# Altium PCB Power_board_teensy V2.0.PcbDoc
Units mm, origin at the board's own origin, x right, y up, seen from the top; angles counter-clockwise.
Board outline 76.2 x 50.8 mm, 2 copper layers (Top, Bottom), stack 1.572 mm thick; 21 components, 7 nets, 53 pads, 0 vias.
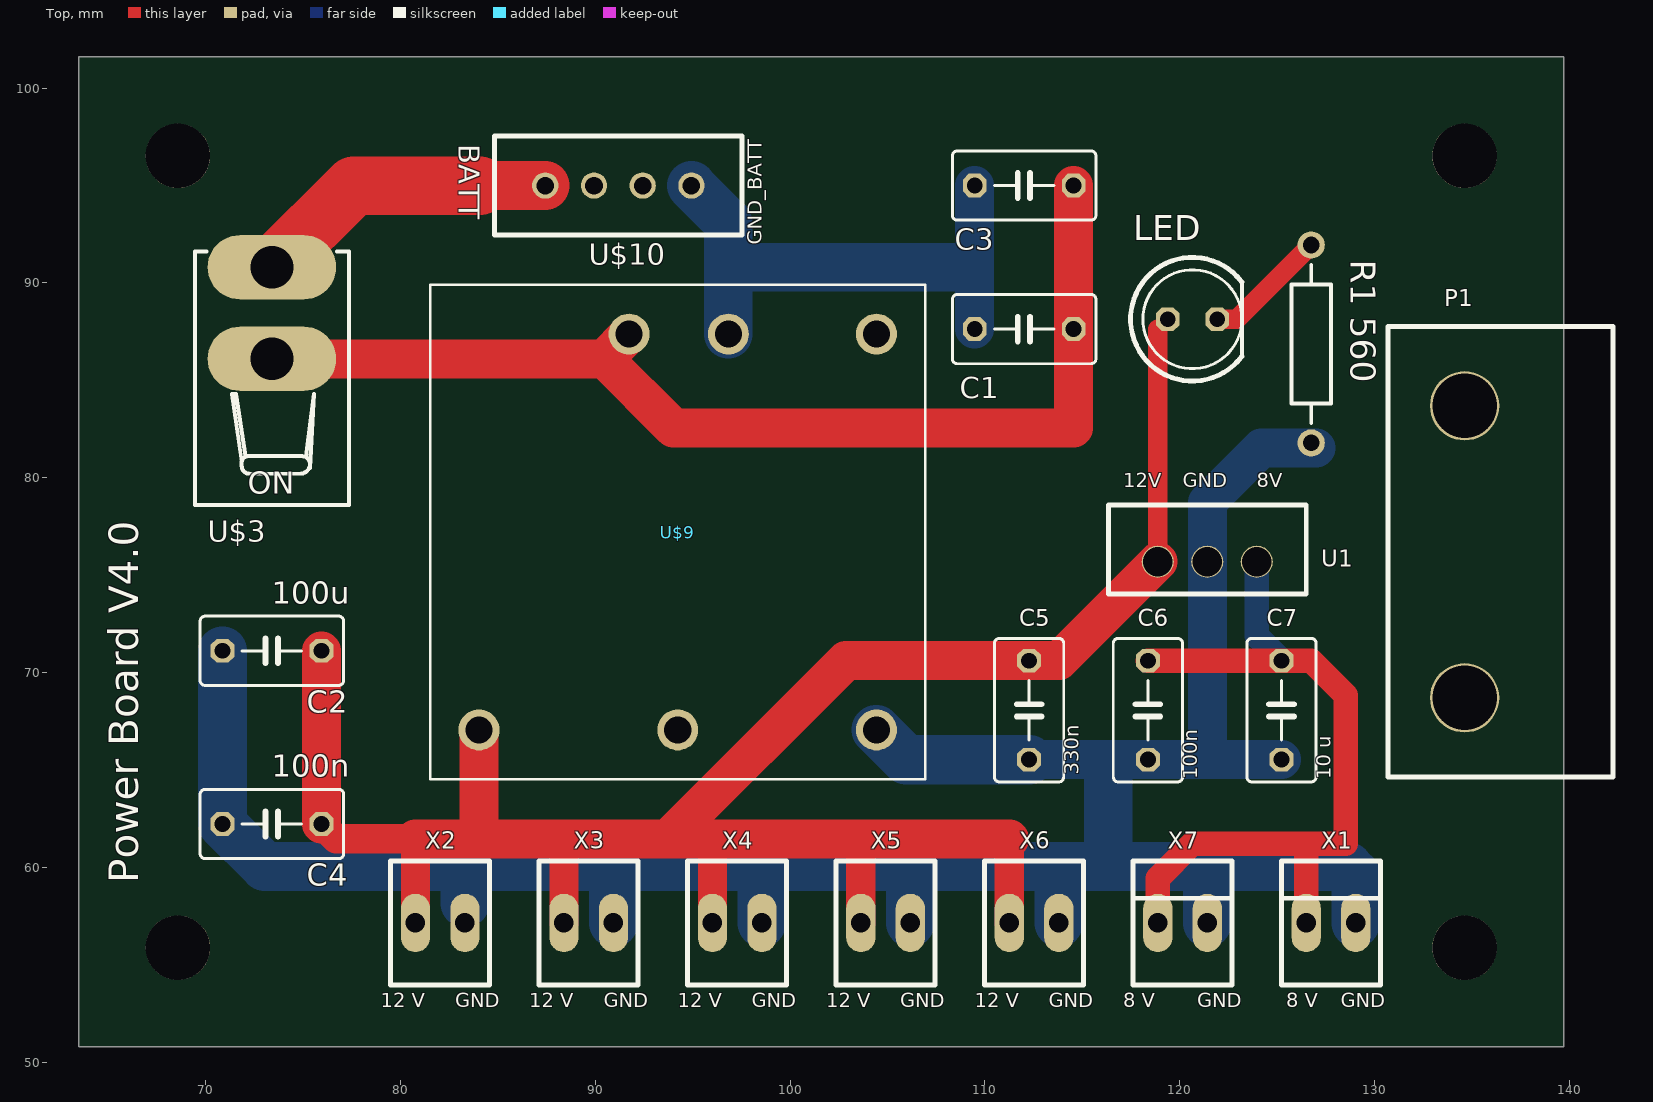
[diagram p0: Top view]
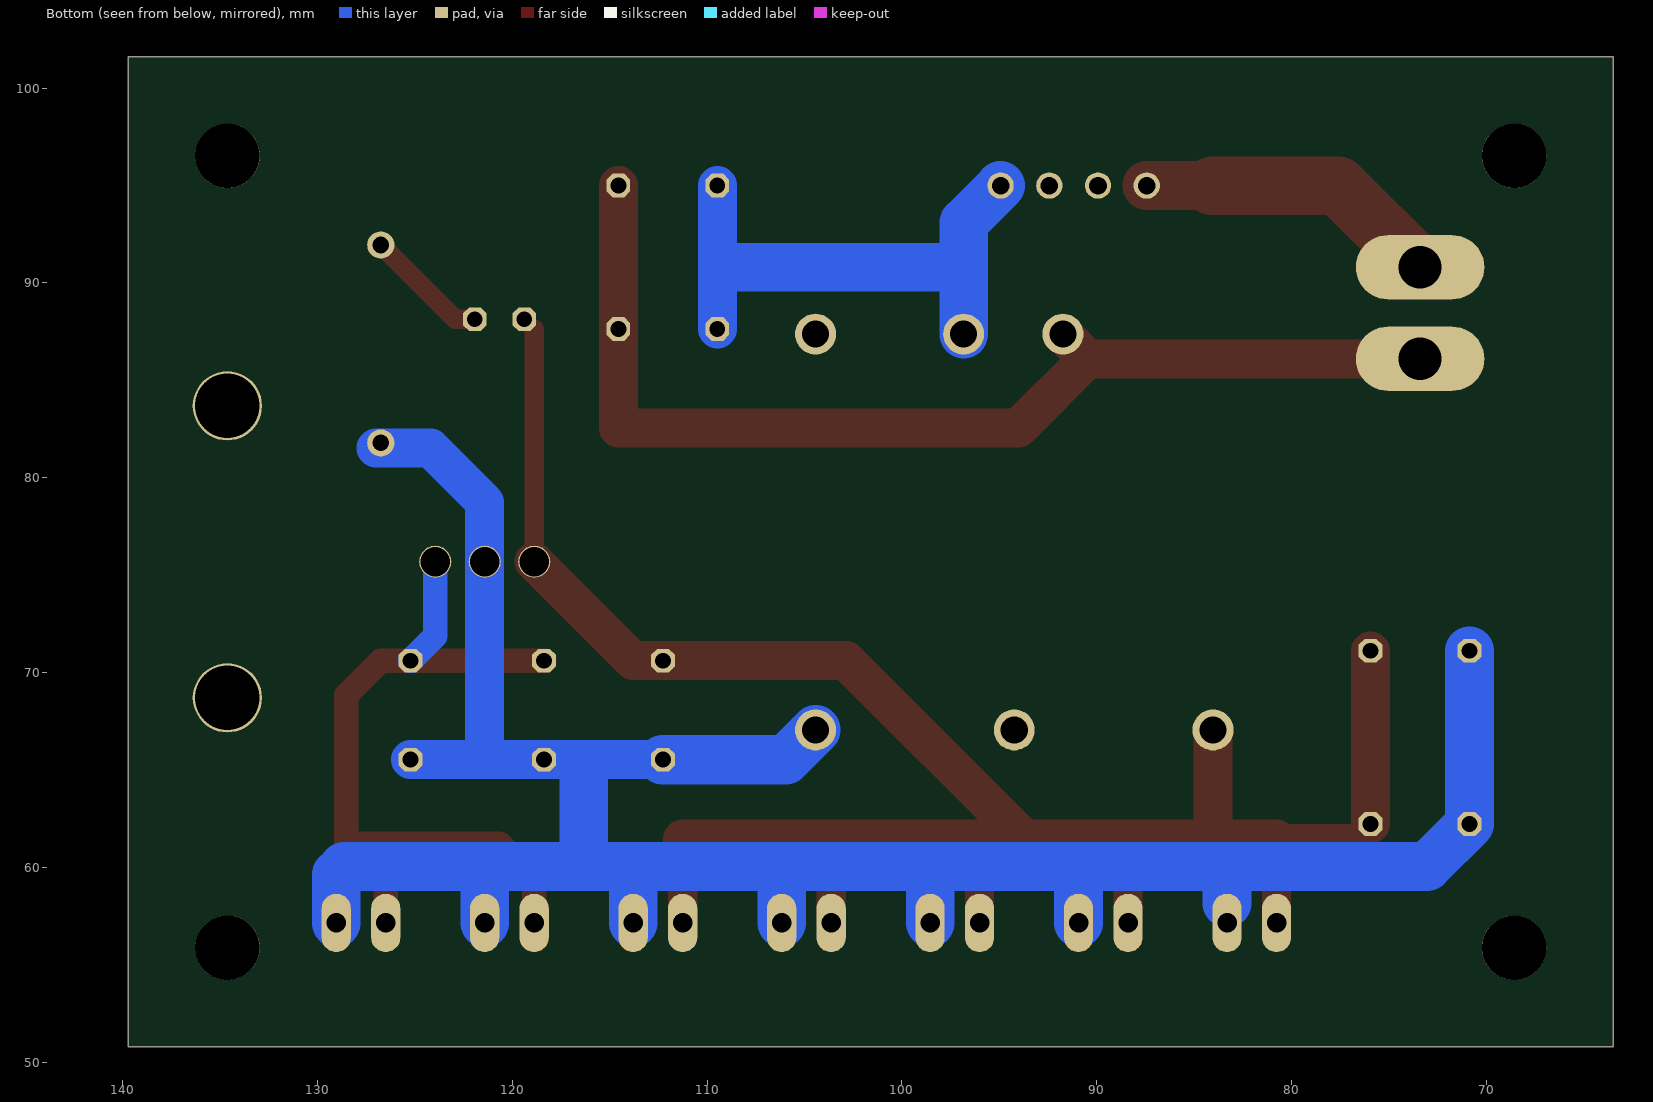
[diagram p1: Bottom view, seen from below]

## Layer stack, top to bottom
Top Solder: solder mask 0.0102, Solder Resist, Dk 3.5
Top: signal copper 0.0356
Dielectric 1: core 1.5011, FR-4, Dk 4.8
Bottom: signal copper 0.0356
Bottom Solder: solder mask 0.0102, Solder Resist, Dk 3.5

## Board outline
63.5,101.6 63.5,50.8 139.7,50.8 139.7,101.6

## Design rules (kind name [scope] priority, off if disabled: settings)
Clearance [All] p1: gap=0.152 ignorepadtopadclearanceinfootprint=TRUE except(0: Arc-Hole Track-Hole SMDPad-SMDPad SMDPad-THPad SMDPad-Via SMDPad-Hole THPad-Hole Via-Hole Fill-Hole Poly-Hole Region-Hole Text-Hole; 1: Arc-Poly Track-Poly SMDPad-Poly THPad-Poly Via-Poly Fill-Poly Poly-Poly)
Clearance "Clearance (Same Net)" [All] p2: gap=0 ignorepadtopadclearanceinfootprint=FALSE except(0.152: SMDPad-SMDPad SMDPad-THPad SMDPad-Via)
HoleSize HoleSize_1 [All] p1: absolutevalues=TRUE maxlimit=2540 minlimit=0.33 maxpercent=80.000 minpercent=20.000
HoleSize [All] p2: absolutevalues=TRUE maxlimit=2.54 minlimit=0.025 maxpercent=80.000 minpercent=20.000
HoleToHoleClearance mdViaViaSameLayer [All] p1: gap=0.203 allowstackedmicrovias=TRUE
HoleToHoleClearance [All] p2: gap=0.254 allowstackedmicrovias=TRUE
PasteMaskExpansion mlMinCreamFrame [All] p1: expansion=0
PasteMaskExpansion [All] p2: expansion=0
PolygonConnect ThermalVias [IsVia] p1: connectstyle=Direct reliefconductorwidth=0.254 reliefentries=4 polygonreliefangle="90 Angle" airgapwidth=0.254
PolygonConnect [All] p2: connectstyle=Direct reliefconductorwidth=0.254 reliefentries=4 polygonreliefangle="90 Angle" airgapwidth=0.254
RoutingVias [All] p1: holewidth=0.711 width=1.27 viastyle="Through Hole" minholewidth=0.711 minwidth=1.27 maxholewidth=0.711 maxwidth=1.27
SilkToSilkClearance [All] p1 off: silktosilkclearance=0.254
SilkToSolderMaskClearance [IsPad] p1 off: minsilkscreentomaskgap=0.254 clearancetoexposedcopper=TRUE
SolderMaskExpansion mlMinStopFrame [All] p1: expansion=0.076
SolderMaskExpansion [All] p2: expansion=0.102
Width Width_1 [All] p1: maxlimit=2540 minlimit=0.152 preferedwidth=0.254
Width [All] p2: maxlimit=2.54 minlimit=0.254 preferedwidth=2.54
25 further rules are at their usual default settings.

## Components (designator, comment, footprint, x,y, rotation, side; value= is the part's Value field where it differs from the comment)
C1 "100u" C050-035X075 112.014,87.63 r180 top
C2 "100u" C050-035X075 73.406,71.12 r180 top
C3 "100n" C050-035X075 112.014,94.996 r180 top
C4 "100n" C050-035X075 73.406,62.23 r180 top
C5 "0.33uF" C050-035X075 112.268,68.072 r270 top
C6 "100nF" C050-035X075 118.364,68.072 r270 top
C7 "10uF" C050-035X075 125.222,68.072 r270 top
LED "PWR" LED5MM 120.65,88.138 r0 top (schematic designator LED1)
P1 "antenna pads" "Antenna pads" 134.62,76.2 r270 top
"R1 560" "" AXIAL-0.4 126.746,86.868 r90 top value=560 (schematic designator R1)
U1 "12V to 8V LDO" BA7808CP-E2 121.412,75.692 r0 top
U$3 "360-3240-ND" 360-3240-ND 69.456,78.606 r0 top
U$9 "12V_TRANSFORMER" 12V_TRANSFORMER 104.434,77.216 r0 top locked
U$10 "BATT" BATTERY_CONNECTOR 91.186,94.996 r180 top
X1 "22-23-2021" 22-23-2021 127.762,57.15 r0 top
X2 "22-23-2021" 22-23-2021 82.042,57.15 r0 top
X3 "22-23-2021" 22-23-2021 89.662,57.15 r0 top
X4 "22-23-2021" 22-23-2021 97.282,57.15 r0 top
X5 "22-23-2021" 22-23-2021 104.902,57.15 r0 top
X6 "22-23-2021" 22-23-2021 112.522,57.15 r0 top
X7 "22-23-2021" 22-23-2021 120.142,57.15 r0 top

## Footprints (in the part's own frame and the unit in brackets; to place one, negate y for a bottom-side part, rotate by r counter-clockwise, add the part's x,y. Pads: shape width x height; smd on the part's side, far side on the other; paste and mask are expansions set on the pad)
12V_TRANSFORMER [mm] "12V_TRANSFORMER"
  round 2.1 hole 1.4: P$1(-12.7,10.16) P$2(-7.6,10.16) P$3(-20.4,-10.16) P$4(-10.2,-10.16) P$5(0,-10.16) P$6(0,10.16)
  silkscreen extent -22.9,-12.7 2.5,12.7
22-23-2021 [mm]
  oval 1.5x3 hole 1: 1(-1.27,0) 2(1.27,0)
  silkscreen extent -2.54,-3.17 2.54,3.17
360-3240-ND [mm] "360-3240-ND"
  oval 6.6x3.3 hole 2.2: 2(3.95,7.5) 3(3.95,12.2)
  silkscreen extent 0,0 7.9,13
"Antenna pads" [mil] "sma connector standoff"
  round 140 hole 130: 1(-295,0) 2(295,0)
  silkscreen extent -455,-155 455,300
AXIAL-0.4 [mm] "Axial Device, Thru-Hole; 2 Leads; 0.4 in Pin Spacing"
  round 1.4 hole 0.85: 1(-5.08,0) 2(5.08,0)
  silkscreen extent -4.06,-1.02 4.06,1.02
BA7808CP-E2 [mil]
  round 65 hole 60: 1(-100,0) 2(0,0) 3(100,0)
  silkscreen extent -200,-65 200,115
BATTERY_CONNECTOR [mm] "BATTERY_CONNECTOR"
  round 1.35 hole 0.9: P$1(-3.75,0) P$2(-1.25,0) P$3(1.25,0) P$4(3.75,0)
  silkscreen extent -6.35,-2.54 6.35,2.54
C050-035X075 [mil] "C050-035X075"
  oct 48x48 hole 32: 1(-100,0) 2(100,0)
  silkscreen extent -145,-70 145,70
LED5MM [mil]
  oct 48x48 hole 32: A(-50,0) K(50,0)
  silkscreen extent -125,-125 100,125, body extent -116,-116 116,116, height 346

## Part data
C1 C2 C3 C4 C5 C6 C7: library part C-US050-035X075, "CAPACITOR, American symbol"
LED: library part LED5MM
"R1 560": library part Res2, "Resistor"
U1: library part BA78M08FP-E2
U$3: "SPST two lead switch Pin 2 is common Swtich Closed on Down Position DigiKey: http://www.digikey.com/product-detail/en/nkk-switches/M2011S2A1W01/360-3240-ND/1049342 Data Sheet: http://2t70un3m1d9z1kztamkdrd38.wpengine.netdna-cdn.com/wp-content/uploads/2016/02/MtogglesBushing.pdf"
U$9: "CUI Inc │ SERIES: PDQ30-D │ DESCRIPTION: DC-DC CONVERTER http://www.mouser.com/pdfdocs/pdq30-d.pdf"
U$10: library part BATTERY_CONNECTOR
X1 X2 X3 X4 X5 X6 X7: ".100\" (2.54mm) Center Header - 2 Pin"

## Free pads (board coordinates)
  round 3.3 hole 3.3: 1(68.58,55.88) 1(68.58,96.52) 1(134.62,55.88) 1(134.62,96.52)

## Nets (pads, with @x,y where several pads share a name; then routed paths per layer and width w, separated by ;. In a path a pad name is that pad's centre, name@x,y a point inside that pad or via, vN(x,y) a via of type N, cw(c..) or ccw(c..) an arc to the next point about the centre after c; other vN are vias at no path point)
GND_12: "R1 560.1" C2.2 C4.2 C5.2 C6.2 C7.2 U1.2 U$9.P$5 X1.2 X2.2 X3.2 X4.2 X5.2 X6.2 X7.2 | length 132.6
  Bottom w0.254: 128.632,60.052 129.032,59.653
  Bottom w1.27: 82.95,60.052 83.312,59.69 ; 121.304,60.052 121.412,59.944
  Bottom w2: C5.2 C6.2 121.412,65.532 ; C7.2 121.412,65.532 ; 127,81.534 124.206,81.534 121.412,78.74 U1.2 121.412,65.532
  Bottom w2.5: C2.2 C4.2 73.044,60.052 82.95,60.052 90.932,60.052 ; X2.2@83.312,58.166 83.312,59.69 ; X3.2 90.932,60.052 ; X4.2 98.552,59.944 ; X5.2 106.172,59.69 ; X6.2 113.792,59.944 113.684,60.052 ; 116.332,64.516 116.332,60.052 ; X7.2 121.412,59.944 ; 128.632,60.052 121.304,60.052 116.332,60.052 ; X1.2 129.032,59.653 ; 90.932,60.052 113.684,60.052 ; 113.684,60.052 116.332,60.052
  Bottom w2.54: U$9.P$5 105.958,65.532 C5.2
GND_BATT: C1.2 C3.2 U$9.P$2 U$10.P$1 | length 27.7
  Bottom w2: C1.2 C3.2
  Bottom w2.5: U$10.P$1 96.834,93.098 96.834,90.806 ; U$9.P$2 96.834,90.806 ; 108.712,90.806 96.834,90.806
MAIN_BATT: C1.1 C3.1 U$3.2 U$9.P$1 | length 56.9
  Top w2: U$3.2 90.464,86.106 ; U$9.P$1 90.464,86.106 ; C3.1 C1.1 114.554,82.55 94.02,82.55 90.464,86.106
NetLED1_K: "R1 560.2" LED.K | length 6.4
  Top w1: LED.K 122.936,88.138 126.746,91.948
V8: C6.1 C7.1 U1.3 X1.1 X7.1 | length 40.9
  Top w1.27: C6.1 C7.1 126.746,70.612 128.524,68.834 128.524,61.214 126.492,61.214 ; X7.1 118.872,59.436 120.65,61.214 126.492,61.214 ; X1.1 126.492,61.214
  Bottom w1.27: U1.3 123.952,71.882 C7.1
V11.2: U$3.3 U$10.P$4 | length 15.8
  Top w2.5: 84.074,94.996 U$10.P$4
  Top w3: U$3.3 77.596,94.996 84.074,94.996
V12: C2.1 C4.1 C5.1 LED.A U1.1 U$9.P$3 X2.1 X3.1 X4.1 X5.1 X6.1 | length 115.6
  Top w0.254: 83.82,61.468 84.034,61.682 ; 88.138,61.468 88.392,61.214 ; 118.872,87.63 LED.A
  Top w1: U1.1 118.872,87.63
  Top w1.5: C4.1 76.708,61.468 80.772,61.468 X2.1 ; X3.1 88.392,61.214 ; X4.1 96.012,61.468 ; X5.1 103.632,61.468 ; X6.1 111.252,61.468
  Top w2: C4.1 C2.1 ; 80.772,61.468 83.82,61.468 88.138,61.468 93.726,61.468 ; 84.034,61.682 U$9.P$3 ; 111.252,61.468 103.632,61.468 96.012,61.468 93.726,61.468 ; U1.1 113.792,70.612 C5.1 102.87,70.612 93.726,61.468
pads on no net: P1.1 P1.2 U$9.P$4 U$9.P$6 U$10.P$2 U$10.P$3

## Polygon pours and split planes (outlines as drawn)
no net on Bottom "Bottom-No Net" (solid, pour order 12): 61.214,80.264

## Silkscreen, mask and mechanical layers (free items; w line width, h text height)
Top Overlay:
  text "GND_BATT" at 98.806,91.948 h1.26 r90
  text "12V" at 117.094,79.248 h1.26
  text "GND" at 120.142,79.248 h1.26
  text "8V" at 123.952,79.248 h1.26
  text "330n" at 115.062,64.77 h1.26 r90
  text "100n" at 121.158,64.516 h1.26 r90
  text "10 u" at 128.016,64.516 h1.26 r90
  text "Power Board V4.0" at 66.548,59.182 h1.52 r90
  text "12 V" at 78.994,52.578 h1.26
  text "GND" at 82.804,52.578 h1.26
  text "12 V" at 86.614,52.578 h1.26
  text "GND" at 90.424,52.578 h1.26
  text "12 V" at 94.234,52.578 h1.26
  text "GND" at 98.044,52.578 h1.26
  text "12 V" at 101.854,52.578 h1.26
  text "GND" at 105.664,52.578 h1.26
  text "12 V" at 109.474,52.578 h1.26
  text "GND" at 113.284,52.578 h1.26
  text "8 V" at 117.094,52.578 h1.26
  text "GND" at 120.904,52.578 h1.26
  text "8 V" at 125.476,52.578 h1.26
  text "GND" at 128.27,52.578 h1.26
Unrouted:
  lines w0: 31.263,50.563 31.263,51.934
